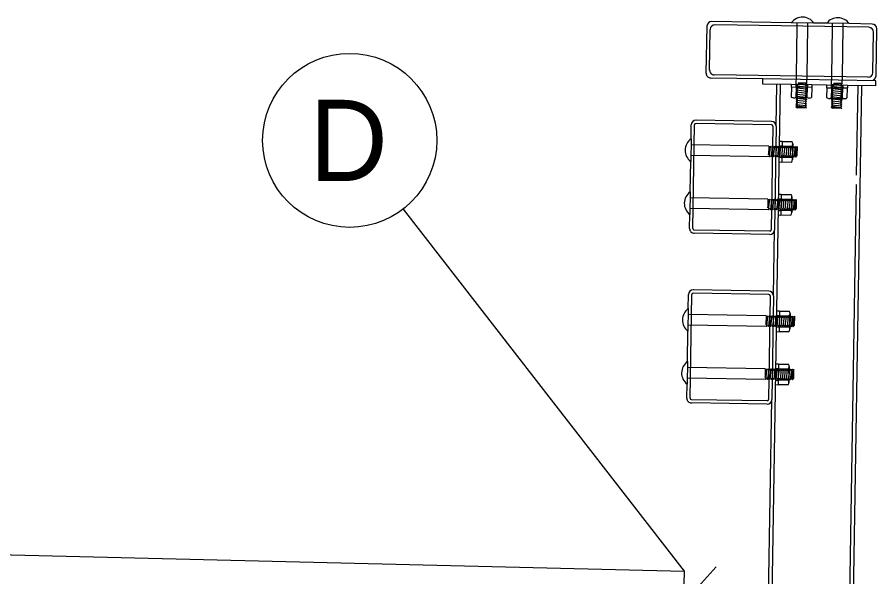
# Model space of a CAD drawing. Extents: x 0 to 1276, y -220 to 347.
# Drawn here: x 144.39 to 159.19, y -183.71 to -174.06 of the extents above; entities that cross this region are included whole.
import ezdxf

# ---------------------------------------------------------------- set-up
doc = ezdxf.new("R2010")
doc.units = 0
for name, color, linetype in [('BR_P_Gen_Waterproofing', 7, 'Continuous'), ('BR_P_Rail_Hidden', 7, 'Continuous'), ('BR_P_Rail_Object', 7, 'Continuous'), ('BR_P_Slab_Object', 7, 'Continuous'), ('TX_P_1', 7, 'Continuous')]:
    doc.layers.add(name, color=color, linetype=linetype)

msp = doc.modelspace()

# ---------------------------------------------------------------- linework, layer by layer
at = {"layer": 'BR_P_Gen_Waterproofing'}
msp.add_line((155.921, -184.091), (156.422, -183.533), dxfattribs=at)
at = {"layer": 'BR_P_Rail_Hidden'}
for p, q in [((157.821, -174.215), (157.822, -174.158)), ((158.004, -174.218), (158.005, -174.161)), ((158.43, -174.224), (158.431, -174.168)), ((158.613, -174.227), (158.614, -174.17)), ((157.805, -175.213), (157.807, -175.076)), ((157.988, -175.197), (157.99, -175.079)), ((158.414, -175.223), (158.417, -175.086)), ((158.597, -175.206), (158.599, -175.089)), ((157.797, -175.224), (157.797, -175.267)), ((157.986, -175.303), (157.804, -175.284)), ((157.988, -175.232), (157.805, -175.213)), ((157.987, -175.268), (157.805, -175.249)), ((157.988, -175.197), (157.838, -175.194)), ((157.838, -175.194), (157.964, -175.214)), ((157.995, -175.227), (157.995, -175.27)), ((158.407, -175.234), (158.406, -175.277)), ((158.596, -175.313), (158.413, -175.294)), ((158.597, -175.242), (158.414, -175.223)), ((158.596, -175.277), (158.414, -175.258)), ((158.597, -175.206), (158.447, -175.204)), ((158.447, -175.204), (158.573, -175.224)), ((158.572, -175.279), (158.573, -175.28)), ((158.605, -175.237), (158.604, -175.28)), ((158.028, -175.456), (157.757, -175.451)), ((157.985, -175.41), (157.802, -175.391)), ((157.984, -175.445), (157.802, -175.426)), ((157.986, -175.339), (157.803, -175.32)), ((157.985, -175.374), (157.803, -175.355)), ((158.593, -175.455), (158.411, -175.436)), ((158.595, -175.384), (158.412, -175.365)), ((158.594, -175.42), (158.412, -175.401)), ((158.595, -175.348), (158.413, -175.33)), ((158.367, -175.461), (158.637, -175.465)), ((157.463, -176.285), (157.451, -176.401)), ((157.498, -176.286), (157.48, -176.468)), ((157.534, -176.286), (157.515, -176.469)), ((157.516, -176.278), (157.559, -176.279)), ((157.57, -176.287), (157.551, -176.469)), ((157.605, -176.287), (157.586, -176.47)), ((157.641, -176.288), (157.622, -176.471)), ((157.676, -176.289), (157.657, -176.471)), ((157.712, -176.289), (157.693, -176.472)), ((157.743, -176.327), (157.728, -176.472)), ((157.745, -176.246), (157.74, -176.516)), ((157.45, -176.46), (157.462, -176.444)), ((157.462, -176.444), (157.463, -176.445)), ((157.513, -176.476), (157.556, -176.477)), ((157.381, -177.204), (157.395, -177.223)), ((157.413, -177.199), (157.394, -177.381)), ((157.395, -177.223), (157.413, -177.199)), ((157.413, -177.199), (157.43, -177.223)), ((157.448, -177.199), (157.429, -177.382)), ((157.484, -177.2), (157.465, -177.382)), ((157.519, -177.2), (157.5, -177.383)), ((157.502, -177.192), (157.545, -177.193)), ((157.555, -177.201), (157.536, -177.383)), ((157.59, -177.201), (157.572, -177.384)), ((157.626, -177.202), (157.607, -177.384)), ((157.662, -177.203), (157.643, -177.385)), ((157.697, -177.203), (157.678, -177.386)), ((157.73, -177.16), (157.726, -177.43)), ((157.379, -177.36), (157.394, -177.381)), ((157.729, -177.241), (157.714, -177.386)), ((157.498, -177.39), (157.542, -177.391)), ((157.349, -179.214), (157.362, -179.233)), ((157.381, -179.209), (157.362, -179.392)), ((157.362, -179.233), (157.381, -179.209)), ((157.381, -179.209), (157.398, -179.234)), ((157.416, -179.21), (157.397, -179.392)), ((157.452, -179.21), (157.433, -179.393)), ((157.466, -179.391), (157.469, -179.235)), ((157.487, -179.211), (157.468, -179.393)), ((157.469, -179.203), (157.513, -179.204)), ((157.523, -179.211), (157.504, -179.394)), ((157.558, -179.212), (157.539, -179.395)), ((157.594, -179.213), (157.575, -179.395)), ((157.629, -179.213), (157.61, -179.396)), ((157.665, -179.214), (157.646, -179.396)), ((157.697, -179.251), (157.682, -179.397)), ((157.698, -179.17), (157.694, -179.441)), ((157.347, -179.37), (157.362, -179.392)), ((157.466, -179.401), (157.509, -179.402)), ((157.334, -180.128), (157.348, -180.147)), ((157.366, -180.123), (157.347, -180.306)), ((157.348, -180.147), (157.366, -180.123)), ((157.366, -180.123), (157.383, -180.148)), ((157.401, -180.124), (157.383, -180.306)), ((157.437, -180.124), (157.418, -180.307)), ((157.452, -180.305), (157.454, -180.149)), ((157.473, -180.125), (157.454, -180.307)), ((157.455, -180.117), (157.498, -180.118)), ((157.508, -180.125), (157.489, -180.308)), ((157.544, -180.126), (157.525, -180.309)), ((157.579, -180.127), (157.56, -180.309)), ((157.615, -180.127), (157.596, -180.31)), ((157.65, -180.128), (157.631, -180.31)), ((157.682, -180.165), (157.667, -180.311)), ((157.683, -180.084), (157.679, -180.355)), ((157.332, -180.284), (157.347, -180.306)), ((157.452, -180.315), (157.495, -180.316))]:
    msp.add_line(p, q, dxfattribs=at)
for points in [[(157.828, -175.268), (157.804, -175.284), (157.828, -175.302), (157.803, -175.32), (157.827, -175.338), (157.803, -175.355), (157.827, -175.373), (157.802, -175.391), (157.826, -175.409), (157.802, -175.426), (157.826, -175.445), (157.815, -175.452)], [(157.805, -175.213), (157.829, -175.231), (157.805, -175.249), (157.829, -175.267), (157.828, -175.268)], [(157.984, -175.27), (157.962, -175.285), (157.986, -175.303), (157.962, -175.321), (157.986, -175.339), (157.961, -175.356), (157.985, -175.374), (157.961, -175.392), (157.985, -175.41), (157.96, -175.427), (157.984, -175.445), (157.971, -175.455)], [(157.988, -175.197), (157.964, -175.214), (157.988, -175.232), (157.963, -175.249)], [(158.437, -175.277), (158.413, -175.294), (158.437, -175.312), (158.413, -175.33), (158.437, -175.348), (158.412, -175.365), (158.436, -175.383), (158.412, -175.401), (158.436, -175.419), (158.411, -175.436), (158.435, -175.454), (158.424, -175.462)], [(158.414, -175.223), (158.438, -175.241), (158.414, -175.258), (158.438, -175.277), (158.437, -175.277)], [(158.593, -175.28), (158.572, -175.295), (158.596, -175.313), (158.571, -175.33), (158.595, -175.348), (158.571, -175.366), (158.595, -175.384), (158.57, -175.401), (158.594, -175.42), (158.569, -175.437), (158.593, -175.455), (158.58, -175.464)], [(158.597, -175.206), (158.573, -175.224), (158.597, -175.242), (158.572, -175.259)], [(157.465, -176.289), (157.48, -176.31), (157.498, -176.286), (157.516, -176.31), (157.534, -176.286), (157.551, -176.311), (157.57, -176.287), (157.587, -176.312), (157.605, -176.287), (157.622, -176.312), (157.641, -176.288), (157.65, -176.301)], [(157.65, -176.301), (157.658, -176.313), (157.676, -176.289), (157.694, -176.313), (157.712, -176.289), (157.729, -176.314), (157.744, -176.294)], [(157.463, -176.445), (157.48, -176.468), (157.498, -176.444), (157.515, -176.469), (157.533, -176.445), (157.551, -176.469), (157.569, -176.445), (157.586, -176.47), (157.604, -176.446), (157.622, -176.471), (157.64, -176.446), (157.647, -176.457)], [(157.647, -176.457), (157.657, -176.471), (157.675, -176.447), (157.693, -176.472), (157.711, -176.448), (157.728, -176.472), (157.741, -176.455)], [(157.451, -177.203), (157.466, -177.224), (157.484, -177.2), (157.501, -177.224), (157.519, -177.2), (157.537, -177.225), (157.555, -177.201), (157.572, -177.225), (157.59, -177.201), (157.608, -177.226), (157.626, -177.202), (157.635, -177.215)], [(157.635, -177.215), (157.643, -177.227), (157.662, -177.203), (157.679, -177.227), (157.697, -177.203), (157.714, -177.228), (157.729, -177.208)], [(157.394, -177.381), (157.412, -177.357), (157.429, -177.382), (157.448, -177.358), (157.448, -177.359)], [(157.448, -177.359), (157.465, -177.382), (157.483, -177.358), (157.5, -177.383), (157.519, -177.359), (157.536, -177.383), (157.554, -177.359), (157.572, -177.384), (157.59, -177.36), (157.607, -177.384), (157.625, -177.36), (157.633, -177.371)], [(157.633, -177.371), (157.643, -177.385), (157.661, -177.361), (157.678, -177.386), (157.696, -177.362), (157.714, -177.386), (157.727, -177.369)], [(157.419, -179.213), (157.433, -179.234), (157.452, -179.21), (157.469, -179.235), (157.487, -179.211), (157.505, -179.236), (157.523, -179.211), (157.54, -179.236), (157.558, -179.212), (157.576, -179.237), (157.594, -179.213), (157.603, -179.226)], [(157.603, -179.226), (157.611, -179.237), (157.629, -179.213), (157.647, -179.238), (157.665, -179.214), (157.682, -179.238), (157.697, -179.219)], [(157.362, -179.392), (157.38, -179.368), (157.397, -179.392), (157.415, -179.368), (157.416, -179.369)], [(157.416, -179.369), (157.433, -179.393), (157.451, -179.369), (157.468, -179.393), (157.486, -179.369), (157.504, -179.394), (157.522, -179.37), (157.539, -179.395), (157.558, -179.37), (157.575, -179.395), (157.593, -179.371), (157.601, -179.382)], [(157.601, -179.382), (157.61, -179.396), (157.629, -179.372), (157.646, -179.396), (157.664, -179.372), (157.682, -179.397), (157.695, -179.38)], [(157.404, -180.127), (157.419, -180.148), (157.437, -180.124), (157.454, -180.149), (157.473, -180.125), (157.49, -180.15), (157.508, -180.125), (157.525, -180.15), (157.544, -180.126), (157.561, -180.151), (157.579, -180.127), (157.589, -180.14)], [(157.589, -180.14), (157.597, -180.151), (157.615, -180.127), (157.632, -180.152), (157.65, -180.128), (157.668, -180.152), (157.682, -180.133)], [(157.347, -180.306), (157.365, -180.282), (157.383, -180.306), (157.401, -180.282), (157.401, -180.283)], [(157.401, -180.283), (157.418, -180.307), (157.436, -180.283), (157.454, -180.307), (157.472, -180.283), (157.489, -180.308), (157.507, -180.284), (157.525, -180.309), (157.543, -180.284), (157.56, -180.309), (157.578, -180.285), (157.586, -180.296)], [(157.586, -180.296), (157.596, -180.31), (157.614, -180.286), (157.631, -180.31), (157.65, -180.286), (157.667, -180.311), (157.68, -180.294)]]:
    msp.add_lwpolyline(points, dxfattribs=at)
for centre, radius, start, end in [((157.759, -175.381), 0.07, 233.594, 304.5727), ((157.898, -175.103), 0.351, 253.4367, 284.73), ((158.029, -175.386), 0.07, 233.594, 304.5727), ((158.368, -175.391), 0.07, 233.594, 304.5727), ((158.508, -175.112), 0.351, 253.4367, 284.73), ((158.638, -175.395), 0.07, 233.594, 304.5727), ((157.392, -176.375), 0.351, 343.4367, 14.73), ((157.675, -176.245), 0.07, 323.594, 34.5727), ((157.67, -176.515), 0.07, 323.594, 34.5727), ((157.377, -177.289), 0.351, 343.4367, 14.73), ((157.66, -177.159), 0.07, 323.594, 34.5727), ((157.656, -177.429), 0.07, 323.594, 34.5727), ((157.628, -179.169), 0.07, 323.594, 34.5727), ((157.345, -179.3), 0.351, 343.4367, 14.73), ((157.624, -179.44), 0.07, 323.594, 34.5727), ((157.33, -180.214), 0.351, 343.4367, 14.73), ((157.613, -180.083), 0.07, 323.594, 34.5727), ((157.609, -180.354), 0.07, 323.594, 34.5727)]:
    msp.add_arc(centre, radius, start, end, dxfattribs=at)
at = {"layer": 'BR_P_Rail_Object'}
for p, q in [((156.254, -175.027), (156.267, -174.214)), ((157.719, -174.156), (156.349, -174.134)), ((159.054, -174.234), (156.405, -174.192)), ((158.108, -174.162), (157.719, -174.156)), ((157.807, -175.076), (157.821, -174.215)), ((157.99, -175.079), (158.004, -174.218)), ((158.328, -174.166), (158.108, -174.162)), ((158.717, -174.172), (158.328, -174.166)), ((158.417, -175.086), (158.43, -174.224)), ((158.599, -175.089), (158.613, -174.227)), ((159.112, -174.178), (158.717, -174.172)), ((159.179, -175.073), (159.192, -174.261)), ((156.312, -174.971), (156.323, -174.272)), ((159.123, -175.016), (159.134, -174.317)), ((157.228, -175.123), (156.334, -175.109)), ((159.04, -175.096), (156.392, -175.053)), ((157.226, -175.215), (157.228, -175.123)), ((159.177, -175.155), (157.228, -175.123)), ((159.176, -175.246), (159.177, -175.155)), ((157.717, -175.223), (157.226, -175.215)), ((157.387, -184.359), (157.533, -175.22)), ((157.458, -175.94), (157.47, -175.219)), ((157.717, -175.223), (157.717, -175.266)), ((158.075, -175.228), (157.717, -175.223)), ((158.075, -175.272), (157.717, -175.266)), ((157.72, -175.266), (157.717, -175.438)), ((157.801, -175.267), (157.798, -175.439)), ((157.99, -175.27), (157.987, -175.442)), ((158.071, -175.271), (158.069, -175.443)), ((158.075, -175.228), (158.075, -175.272)), ((158.327, -175.232), (158.075, -175.228)), ((158.327, -175.232), (158.326, -175.276)), ((158.326, -175.276), (158.684, -175.281)), ((158.329, -175.276), (158.326, -175.447)), ((158.685, -175.238), (158.327, -175.232)), ((158.41, -175.277), (158.408, -175.449)), ((158.6, -175.28), (158.597, -175.452)), ((158.681, -175.281), (158.678, -175.453)), ((158.685, -175.238), (158.684, -175.281)), ((159.176, -175.246), (158.685, -175.238)), ((158.722, -188.403), (158.932, -175.242)), ((158.844, -176.785), (158.869, -175.241)), ((157.982, -175.588), (157.799, -175.569)), ((157.982, -175.552), (157.8, -175.533)), ((157.984, -175.481), (157.801, -175.462)), ((157.983, -175.516), (157.801, -175.498)), ((157.823, -175.587), (157.949, -175.607)), ((158.592, -175.562), (158.409, -175.543)), ((158.591, -175.597), (158.409, -175.578)), ((158.593, -175.491), (158.41, -175.472)), ((158.592, -175.526), (158.41, -175.507)), ((158.433, -175.597), (158.558, -175.616)), ((157.799, -175.604), (157.949, -175.607)), ((157.981, -175.623), (157.823, -175.621)), ((158.408, -175.614), (158.558, -175.616)), ((158.591, -175.633), (158.432, -175.63)), ((157.378, -175.857), (156.078, -175.836)), ((157.377, -175.914), (156.078, -175.893)), ((155.992, -176.159), (155.996, -175.916)), ((156.024, -177.705), (156.053, -175.917)), ((157.401, -175.939), (157.373, -177.726)), ((157.458, -175.94), (157.43, -177.727)), ((155.992, -176.159), (155.986, -176.547)), ((157.331, -176.283), (155.99, -176.262)), ((157.331, -176.283), (157.328, -176.433)), ((157.328, -176.433), (157.356, -176.283)), ((157.356, -176.283), (157.337, -176.466)), ((157.374, -176.308), (157.356, -176.283)), ((157.392, -176.284), (157.373, -176.467)), ((157.392, -176.284), (157.374, -176.308)), ((157.392, -176.284), (157.409, -176.309)), ((157.427, -176.285), (157.408, -176.467)), ((157.409, -176.309), (157.427, -176.285)), ((157.427, -176.285), (157.445, -176.309)), ((157.453, -176.299), (157.445, -176.309)), ((157.517, -176.198), (157.561, -176.199)), ((157.561, -176.199), (157.555, -176.557)), ((157.559, -176.283), (157.731, -176.286)), ((157.561, -176.202), (157.732, -176.205)), ((157.747, -176.29), (157.743, -176.327)), ((157.783, -176.29), (157.764, -176.473)), ((157.782, -176.449), (157.802, -176.323)), ((157.799, -176.473), (157.802, -176.323)), ((157.818, -176.291), (157.816, -176.449)), ((157.337, -176.466), (155.987, -176.444)), ((157.337, -176.466), (157.356, -176.442)), ((157.356, -176.442), (157.373, -176.467)), ((157.373, -176.467), (157.391, -176.442)), ((157.391, -176.442), (157.408, -176.467)), ((157.408, -176.467), (157.427, -176.443)), ((157.427, -176.443), (157.444, -176.468)), ((157.451, -176.401), (157.444, -176.468)), ((157.45, -176.46), (157.444, -176.468)), ((157.556, -176.473), (157.728, -176.475)), ((155.977, -177.073), (155.986, -176.547)), ((157.512, -176.556), (157.555, -176.557)), ((157.555, -176.554), (157.727, -176.557)), ((155.977, -177.073), (155.971, -177.461)), ((158.658, -188.402), (158.841, -176.947)), ((157.316, -177.197), (155.976, -177.176)), ((157.316, -177.197), (157.314, -177.347)), ((157.314, -177.347), (157.342, -177.197)), ((157.342, -177.197), (157.323, -177.38)), ((157.377, -177.198), (157.358, -177.38)), ((157.377, -177.198), (157.381, -177.204)), ((157.503, -177.112), (157.546, -177.113)), ((157.546, -177.113), (157.54, -177.471)), ((157.545, -177.197), (157.716, -177.2)), ((157.546, -177.116), (157.718, -177.119)), ((157.733, -177.204), (157.729, -177.241)), ((157.768, -177.204), (157.749, -177.387)), ((157.804, -177.205), (157.801, -177.363)), ((157.323, -177.38), (155.973, -177.358)), ((157.323, -177.38), (157.341, -177.356)), ((157.341, -177.356), (157.358, -177.38)), ((157.358, -177.38), (157.376, -177.356)), ((157.376, -177.356), (157.379, -177.36)), ((157.767, -177.363), (157.787, -177.237)), ((157.785, -177.387), (157.787, -177.237)), ((155.967, -177.704), (155.971, -177.461)), ((157.497, -177.47), (157.54, -177.471)), ((157.54, -177.468), (157.712, -177.471)), ((157.542, -177.387), (157.713, -177.389)), ((157.347, -177.807), (156.047, -177.786)), ((157.348, -177.75), (156.048, -177.729)), ((157.411, -178.864), (157.43, -177.727)), ((155.945, -179.083), (155.949, -178.841)), ((155.977, -180.629), (156.006, -178.842)), ((157.331, -178.839), (156.031, -178.818)), ((157.332, -178.782), (156.032, -178.761)), ((157.355, -178.863), (157.326, -180.651)), ((157.411, -178.864), (157.383, -180.652)), ((155.945, -179.083), (155.939, -179.472)), ((157.471, -179.123), (157.514, -179.124)), ((157.514, -179.124), (157.508, -179.482)), ((157.514, -179.127), (157.686, -179.13)), ((157.284, -179.208), (155.944, -179.186)), ((157.284, -179.208), (157.282, -179.358)), ((157.282, -179.358), (157.309, -179.208)), ((157.309, -179.208), (157.291, -179.391)), ((157.345, -179.209), (157.326, -179.391)), ((157.345, -179.209), (157.349, -179.214)), ((157.512, -179.208), (157.684, -179.211)), ((157.7, -179.214), (157.697, -179.251)), ((157.736, -179.215), (157.717, -179.397)), ((157.735, -179.373), (157.755, -179.248)), ((157.753, -179.398), (157.755, -179.248)), ((157.772, -179.215), (157.769, -179.374)), ((157.291, -179.391), (155.941, -179.369)), ((157.291, -179.391), (157.309, -179.367)), ((157.309, -179.367), (157.326, -179.391)), ((157.326, -179.391), (157.344, -179.367)), ((157.344, -179.367), (157.347, -179.37)), ((157.509, -179.397), (157.681, -179.4)), ((155.931, -179.997), (155.939, -179.472)), ((157.465, -179.481), (157.508, -179.482)), ((157.508, -179.479), (157.68, -179.481)), ((155.931, -179.997), (155.924, -180.386)), ((157.456, -180.037), (157.499, -180.038)), ((157.499, -180.038), (157.493, -180.396)), ((157.499, -180.041), (157.671, -180.044)), ((157.269, -180.122), (155.929, -180.1)), ((157.269, -180.122), (157.267, -180.272)), ((157.267, -180.272), (157.295, -180.122)), ((157.295, -180.122), (157.276, -180.305)), ((157.33, -180.123), (157.311, -180.305)), ((157.33, -180.123), (157.334, -180.128)), ((157.498, -180.122), (157.67, -180.125)), ((157.686, -180.128), (157.682, -180.165)), ((157.721, -180.129), (157.702, -180.311)), ((157.721, -180.287), (157.74, -180.162)), ((157.738, -180.312), (157.74, -180.162)), ((157.757, -180.129), (157.754, -180.288)), ((157.276, -180.305), (155.926, -180.283)), ((157.276, -180.305), (157.294, -180.28)), ((157.294, -180.28), (157.311, -180.305)), ((157.311, -180.305), (157.33, -180.281)), ((157.33, -180.281), (157.332, -180.284)), ((157.495, -180.311), (157.667, -180.314)), ((155.921, -180.628), (155.924, -180.386)), ((157.45, -180.395), (157.493, -180.396)), ((157.494, -180.392), (157.665, -180.395)), ((157.3, -180.732), (156, -180.711)), ((157.301, -180.675), (156.001, -180.654)), ((157.259, -188.38), (157.383, -180.652))]:
    msp.add_line(p, q, dxfattribs=at)
for points in [[(157.963, -175.249), (157.987, -175.268), (157.984, -175.27)], [(158.572, -175.259), (158.596, -175.277), (158.593, -175.28)], [(157.815, -175.452), (157.801, -175.462), (157.825, -175.48), (157.801, -175.498), (157.825, -175.516), (157.8, -175.533), (157.824, -175.551), (157.799, -175.569), (157.823, -175.587), (157.799, -175.604), (157.823, -175.621)], [(157.971, -175.455), (157.96, -175.463), (157.984, -175.481), (157.959, -175.498), (157.983, -175.516), (157.958, -175.534), (157.982, -175.552), (157.958, -175.569), (157.982, -175.588), (157.957, -175.605), (157.981, -175.623)], [(158.424, -175.462), (158.41, -175.472), (158.434, -175.49), (158.41, -175.507), (158.434, -175.525), (158.409, -175.543), (158.433, -175.561), (158.409, -175.578), (158.433, -175.597), (158.408, -175.614), (158.432, -175.63)], [(158.58, -175.464), (158.569, -175.472), (158.593, -175.491), (158.568, -175.508), (158.592, -175.526), (158.568, -175.544), (158.592, -175.562), (158.567, -175.579), (158.591, -175.597), (158.567, -175.615), (158.591, -175.633)], [(157.453, -176.299), (157.463, -176.285), (157.465, -176.289)], [(157.744, -176.294), (157.747, -176.29), (157.765, -176.314), (157.783, -176.29), (157.8, -176.315), (157.818, -176.291)], [(157.741, -176.455), (157.746, -176.448), (157.764, -176.473), (157.782, -176.449), (157.799, -176.473), (157.816, -176.449)], [(157.377, -177.198), (157.359, -177.222), (157.342, -177.197)], [(157.43, -177.223), (157.448, -177.199), (157.451, -177.203)], [(157.729, -177.208), (157.733, -177.204), (157.75, -177.228), (157.768, -177.204), (157.786, -177.229), (157.804, -177.205)], [(157.727, -177.369), (157.732, -177.362), (157.749, -177.387), (157.767, -177.363), (157.785, -177.387), (157.801, -177.363)], [(157.345, -179.209), (157.327, -179.233), (157.309, -179.208)], [(157.398, -179.234), (157.416, -179.21), (157.419, -179.213)], [(157.697, -179.219), (157.7, -179.214), (157.718, -179.239), (157.736, -179.215), (157.753, -179.24), (157.772, -179.215)], [(157.695, -179.38), (157.7, -179.373), (157.717, -179.397), (157.735, -179.373), (157.753, -179.398), (157.769, -179.374)], [(157.33, -180.123), (157.312, -180.147), (157.295, -180.122)], [(157.383, -180.148), (157.401, -180.124), (157.404, -180.127)], [(157.682, -180.133), (157.686, -180.128), (157.703, -180.153), (157.721, -180.129), (157.739, -180.153), (157.757, -180.129)], [(157.68, -180.294), (157.685, -180.287), (157.702, -180.311), (157.721, -180.287), (157.738, -180.312), (157.754, -180.288)]]:
    msp.add_lwpolyline(points, dxfattribs=at)
for centre, radius, start, end in [((157.911, -174.3), 0.24, 35.0938, 143.0729), ((158.52, -174.31), 0.24, 35.0938, 143.0729), ((156.348, -174.215), 0.0812, 89.0833, 179.0833), ((156.404, -174.273), 0.0812, 89.0833, 179.0833), ((159.053, -174.316), 0.0812, 359.0833, 89.0833), ((159.11, -174.26), 0.0812, 359.0833, 89.0833), ((156.393, -174.972), 0.0812, 179.0833, 269.0833), ((156.335, -175.028), 0.0812, 179.0833, 269.0833), ((159.041, -175.014), 0.0812, 269.0833, 359.0833), ((159.097, -175.072), 0.0812, 269.0833, 359.0833), ((156.077, -175.918), 0.0812, 89.0833, 179.0833), ((156.077, -175.918), 0.0245, 89.0833, 179.0833), ((157.377, -175.938), 0.0812, 359.0833, 89.0833), ((157.377, -175.938), 0.0245, 359.0833, 89.0833), ((156.13, -176.355), 0.24, 125.0938, 233.0729), ((156.116, -177.269), 0.24, 125.0938, 233.0729), ((156.049, -177.705), 0.0812, 179.0833, 269.0833), ((156.049, -177.705), 0.0245, 179.0833, 269.0833), ((156.049, -177.705), 0.0245, 179.0833, 269.0833), ((157.348, -177.726), 0.0812, 269.0833, 359.0833), ((157.348, -177.726), 0.0245, 269.0833, 359.0833), ((156.03, -178.842), 0.0812, 89.0833, 179.0833), ((156.03, -178.842), 0.0245, 89.0833, 179.0833), ((157.33, -178.863), 0.0245, 359.0833, 89.0833), ((157.33, -178.863), 0.0812, 359.0833, 89.0833), ((156.083, -179.28), 0.24, 125.0938, 233.0729), ((156.069, -180.194), 0.24, 125.0938, 233.0729), ((156.002, -180.63), 0.0812, 179.0833, 269.0833), ((156.002, -180.63), 0.0245, 179.0833, 269.0833), ((156.002, -180.63), 0.0245, 179.0833, 269.0833), ((157.302, -180.65), 0.0812, 269.0833, 359.0833), ((157.302, -180.65), 0.0245, 269.0833, 359.0833)]:
    msp.add_arc(centre, radius, start, end, dxfattribs=at)
at = {"layer": 'BR_P_Slab_Object'}
for p, q in [((29.873, -180.585), (155.873, -183.609)), ((155.873, -183.609), (155.753, -188.606))]:
    msp.add_line(p, q, dxfattribs=at)
at = {"layer": 'TX_P_1'}
msp.add_line((151.033, -177.37), (155.873, -183.609), dxfattribs=at)
msp.add_circle((150.113, -176.184), 1.5, dxfattribs=at)

# ---------------------------------------------------------------- texts
msp.add_text('D', height=1.4, dxfattribs=at).set_placement((149.417, -176.884))

doc.saveas('drawing.dxf')
